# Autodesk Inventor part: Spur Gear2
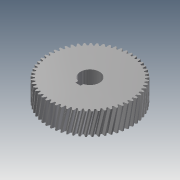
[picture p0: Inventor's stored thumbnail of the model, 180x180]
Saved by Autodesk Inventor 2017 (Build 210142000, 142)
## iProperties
Created: 2019-03
Part Number: Spur Gear2
Material: Steel
Document SubType Name: Modeling
Designer: user
Categories: <?xml version="1.0" encoding="UTF-16"?> <MemberInstance><Categories><FamilyTemplate><FamilyTemplateParameter ValueType="xs:double" Id="1" ObjectReferenceKey="da
Density: 1 g/cm^3
Appearance: Steel
CustomPartVersion: 1
Author: user
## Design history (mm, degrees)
sketch "Sketch1"
  geometry: C1 r 56.952 at (0, 0)
  constraints: 1 centre point
  dimensions: "d0" = 113.90425 diameter of C1 (= da_da)
extrude "Extrusion1" new body sketch "Sketch1" distance "d1" = 30 (= da_b); taper "d2" = 0 deg
workplane "Work Plane2"
sketch "Sketch2"
  geometry: C1 r 56.952 at (0, 0) reference; C2 r 56.337 at (0, 0)
  constraints: 1 centre point, 1 coincident
  dimensions: "d3" = 112.67442 diameter of C2 (= da_dw)
feature "Pitch Diameter" sketch "Sketch2" dims "d4" = 10, "d5" = 0
workplane "Work Plane8"
workplane "Work Plane9"
feature "Spur Gear" dims "da_b" = 30, "da_d" = 116.54683, "da_aw" = 85, "da_da" = 113.90425, "da_df" = 105.70541, "da_dw" = 112.67442, angle "da_beta" = 12 deg, "da_lefttooth" = 0, "da_righttooth" = 10
sketch "Sketch3"
  geometry: L1 (-3.483, -12.525)-(-3.483, -16.267); L2 (-3.483, -16.267)-(3.483, -16.267); L3 (3.483, -16.267)-(3.483, -12.525); A1 r 13 centre (0, 0) between (3.483, -12.525) and (-3.483, -12.525); 2 further points
  constraints: 6 end point, 2 point on circle, 1 centre point, 1 coincident, 1 midpoint, 1 parallel, 1 vertical alignment
  dimensions: "d49" = 26 diameter of A1
extrude "Extrusion2" cut sketch "Sketch3" stored distance "d50" = 10; taper "d51" = 0 deg
body "Solid1"
body "Srf1"
other parameters: "d16" = 85 (= da_aw), "d17" = 0, "d34" = 0.55116 (computed from da_z), "d39" = 0, "d41" = 0, "d43" = 85 (= da_aw), "d46" = 85 (= da_aw), "d47" = 0, "d48" = 0
